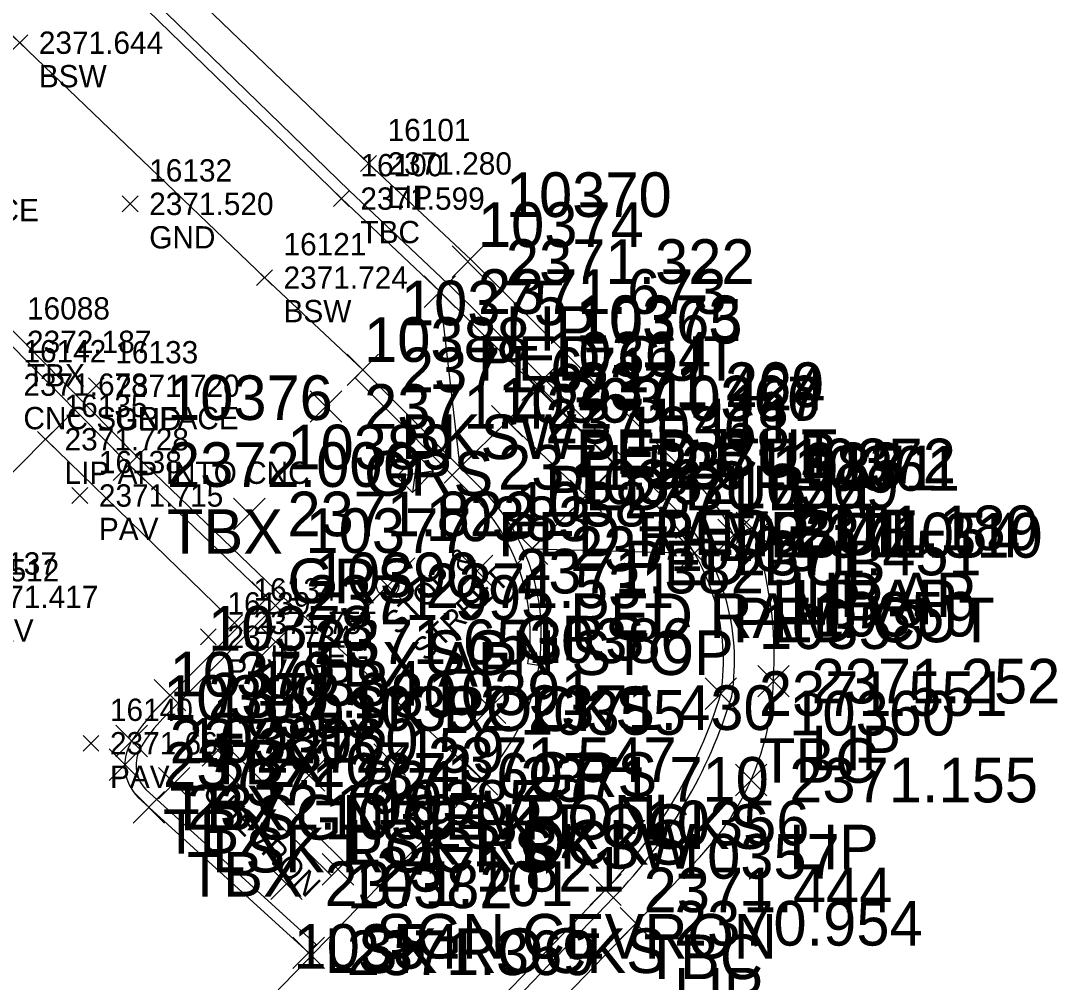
# Model space of a CAD drawing. Extents: x 2377639 to 2379738, y 729875 to 732734.
# Drawn here: x 2378998.89 to 2379045.39, y 731300.7 to 731343.8 of the extents above; entities that cross this region are included whole.
import ezdxf

# ---------------------------------------------------------------- set-up
doc = ezdxf.new("R2010")
doc.units = 0
for name, color, linetype in [('Default', 7, 'Continuous'), ('TOPO_CURBGTR_Back-of-Curb', 7, 'Continuous'), ('TOPO_CURBGTR_Face-of-Curb', 7, 'Continuous'), ('TOPO_CURBGTR_Lip-of-Gutter', 7, 'Continuous'), ('TOPO_DATA_Elevations', 7, 'Continuous'), ('TOPO_DATA_Notes', 7, 'Continuous'), ('TOPO_LNDSCP_Misc', 7, 'Continuous'), ('TOPO_SIGNS_Post-Single', 7, 'Continuous'), ('TOPO_STRUCT_Concrete-Wall', 7, 'Continuous'), ('TOPO_SW_Back', 7, 'Continuous'), ('TOPO_WTRUTIL_Irrig-Box', 7, 'Continuous'), ('TRAF_SIGN_Post', 7, 'Continuous')]:
    doc.layers.add(name, color=color, linetype=linetype)

# ---------------------------------------------------------------- blocks, each defined once
blk = doc.blocks.new('SPRBOX_5')
at = {"layer": 'Default'}
for p, q in [((-0.00857, -0.00643), (0.00857, 0.00643)), ((-0.00857, 0.00643), (0.00857, -0.00643)), ((-0.00857, 0.00643), (0.00857, 0.00643)), ((-0.00857, 0.00643), (-0.00857, -0.00643)), ((0.00857, 0.00643), (0.00857, -0.00643)), ((-0.00857, -0.00643), (0.00857, -0.00643))]:
    blk.add_line(p, q, dxfattribs=at)
blk = doc.blocks.new('STSIGN_4')
at = {"layer": 'Default'}
for p, q in [((0, 0.02226), (0, 0.00635)), ((-0.02226, 0), (-0.00635, 0)), ((0.00635, 0), (0.02226, 0)), ((0, -0.00635), (0, -0.02226))]:
    blk.add_line(p, q, dxfattribs=at)
blk.add_circle((0, 0), 0.00635, dxfattribs=at)

msp = doc.modelspace()

# ---------------------------------------------------------------- linework, layer by layer
at = {"layer": 'TOPO_CURBGTR_Back-of-Curb'}
msp.add_line((2379027.994, 731321.467), (2379017.695, 731331.657), dxfattribs=at)
for points in [[(2378987.114, 731360.909), (2378999.456, 731349.257), (2379013.276, 731335.825), (2379017.695, 731331.657)], [(2378840.2, 731111.439), (2378906.503, 731181.634), (2378954.242, 731230.799), (2378996.057, 731274.46), (2379017.149, 731296.554), (2379025.127, 731304.837)]]:
    msp.add_lwpolyline(points, dxfattribs=at)
for centre, radius, start, end in [((2379020.813, 731315.098), 9.599, 351.2473, 41.5732), ((2379009.353, 731320.03), 21.901, 316.0745, 343.0279)]:
    msp.add_arc(centre, radius, start, end, dxfattribs=at)
at = {"layer": 'TOPO_CURBGTR_Face-of-Curb'}
msp.add_line((2379028.357, 731321.811), (2379018.047, 731332.012), dxfattribs=at)
for points in [[(2378987.457, 731361.273), (2378999.802, 731349.618), (2379013.622, 731336.186), (2379018.038, 731332.021)], [(2378840.546, 731111.077), (2378906.864, 731181.288), (2378954.602, 731230.452), (2378996.418, 731274.114), (2379017.51, 731296.208), (2379025.487, 731304.49)]]:
    msp.add_lwpolyline(points, dxfattribs=at)
for centre, radius, start, end in [((2379020.813, 731315.098), 10.099, 351.042, 41.6668), ((2379009.353, 731320.03), 22.401, 316.0745, 343.1192)]:
    msp.add_arc(centre, radius, start, end, dxfattribs=at)
at = {"layer": 'TOPO_CURBGTR_Lip-of-Gutter'}
for p, q in [((2379029.445, 731322.845), (2379019.102, 731333.079)), ((2379031.697, 731321.064), (2379030.871, 731320.744))]:
    msp.add_line(p, q, dxfattribs=at)
for points in [[(2379019.102, 731333.079), (2379014.495, 731337.4), (2379000.587, 731350.771), (2378988.398, 731362.548)], [(2378843.135, 731111.727), (2378912.115, 731183.979), (2378955.614, 731229.49), (2378997.646, 731273.379), (2379018.593, 731295.17), (2379029.349, 731306.307)]]:
    msp.add_lwpolyline(points, dxfattribs=at)
for centre, radius, start, end in [((2379023.675, 731317.394), 7.938, 24.9615, 43.3723), ((2379015.27, 731315.257), 17.423, 356.507, 19.4705), ((2379020.643, 731314.602), 12.025, 316.386, 358.0598)]:
    msp.add_arc(centre, radius, start, end, dxfattribs=at)
at = {"layer": 'TOPO_DATA_Elevations'}
for p, q in [((2378998.498, 731342.459), (2378999.206, 731343.167)), ((2378998.498, 731343.167), (2378999.206, 731342.459)), ((2378998.498, 731342.459), (2378999.206, 731343.167)), ((2378998.498, 731343.167), (2378999.206, 731342.459)), ((2379014.141, 731337.046), (2379014.849, 731337.754)), ((2379014.141, 731337.754), (2379014.849, 731337.046)), ((2379014.141, 731337.046), (2379014.849, 731337.754)), ((2379014.141, 731337.754), (2379014.849, 731337.046)), ((2379012.922, 731335.471), (2379013.63, 731336.179)), ((2379012.922, 731336.179), (2379013.63, 731335.471)), ((2379012.922, 731335.471), (2379013.63, 731336.179)), ((2379012.922, 731336.179), (2379013.63, 731335.471)), ((2379003.449, 731335.235), (2379004.157, 731335.943)), ((2379003.449, 731335.943), (2379004.157, 731335.235)), ((2379003.449, 731335.235), (2379004.157, 731335.943)), ((2379003.449, 731335.943), (2379004.157, 731335.235)), ((2379018.241, 731332.295), (2379019.655, 731333.709)), ((2379018.241, 731333.709), (2379019.655, 731332.295)), ((2379009.473, 731331.927), (2379010.181, 731332.635)), ((2379009.473, 731332.635), (2379010.181, 731331.927)), ((2379009.473, 731331.927), (2379010.181, 731332.635)), ((2379009.473, 731332.635), (2379010.181, 731331.927)), ((2379016.988, 731330.95), (2379018.402, 731332.364)), ((2379016.988, 731332.364), (2379018.402, 731330.95)), ((2379013.535, 731327.44), (2379014.949, 731328.854)), ((2379013.535, 731328.854), (2379014.949, 731327.44)), ((2379021.373, 731326.775), (2379022.787, 731328.189)), ((2379021.373, 731328.189), (2379022.787, 731326.775)), ((2379001.928, 731327.084), (2379002.636, 731327.792)), ((2379001.928, 731327.792), (2379002.636, 731327.084)), ((2379001.928, 731327.084), (2379002.636, 731327.792)), ((2379001.928, 731327.792), (2379002.636, 731327.084)), ((2379021.416, 731326.62), (2379022.83, 731328.034)), ((2379021.416, 731328.034), (2379022.83, 731326.62)), ((2379011.881, 731325.799), (2379013.295, 731327.213)), ((2379011.881, 731327.213), (2379013.295, 731325.799)), ((2379020.007, 731325.142), (2379021.421, 731326.556)), ((2379020.007, 731326.556), (2379021.421, 731325.142)), ((2378999.652, 731324.682), (2379000.36, 731325.39)), ((2378999.652, 731325.39), (2379000.36, 731324.682)), ((2378999.652, 731324.682), (2379000.36, 731325.39)), ((2378999.652, 731325.39), (2379000.36, 731324.682)), ((2379003.042, 731323.194), (2379004.456, 731324.608)), ((2379003.042, 731324.608), (2379004.456, 731323.194)), ((2379017.892, 731323.075), (2379019.306, 731324.489)), ((2379017.892, 731324.489), (2379019.306, 731323.075)), ((2379024.887, 731323.179), (2379026.301, 731324.593)), ((2379024.887, 731324.593), (2379026.301, 731323.179)), ((2379024.906, 731323.141), (2379026.32, 731324.555)), ((2379024.906, 731324.555), (2379026.32, 731323.141)), ((2379023.537, 731321.787), (2379024.951, 731323.201)), ((2379023.537, 731323.201), (2379024.951, 731321.787)), ((2379001.192, 731322.161), (2379001.9, 731322.869)), ((2379001.192, 731322.869), (2379001.9, 731322.161)), ((2379001.192, 731322.161), (2379001.9, 731322.869)), ((2379001.192, 731322.869), (2379001.9, 731322.161)), ((2379008.443, 731320.982), (2379009.857, 731322.396)), ((2379008.443, 731322.396), (2379009.857, 731320.982)), ((2379030.99, 731320.357), (2379032.404, 731321.771)), ((2379030.99, 731321.771), (2379032.404, 731320.357)), ((2379030.164, 731320.037), (2379031.578, 731321.451)), ((2379030.164, 731321.451), (2379031.578, 731320.037)), ((2379031.163, 731320.023), (2379032.577, 731321.437)), ((2379031.163, 731321.437), (2379032.577, 731320.023)), ((2379021.129, 731319.421), (2379022.543, 731320.835)), ((2379021.129, 731320.835), (2379022.543, 731319.421)), ((2379028.426, 731319.229), (2379029.84, 731320.643)), ((2379028.426, 731320.643), (2379029.84, 731319.229)), ((2379018.661, 731318.42), (2379020.075, 731319.834)), ((2379018.661, 731319.834), (2379020.075, 731318.42)), ((2379014.644, 731317.762), (2379016.058, 731319.176)), ((2379014.644, 731319.176), (2379016.058, 731317.762)), ((2379009.256, 731317.235), (2379010.67, 731318.649)), ((2379009.256, 731318.649), (2379010.67, 731317.235)), ((2379008.131, 731316.451), (2379008.839, 731317.159)), ((2379008.131, 731317.159), (2379008.839, 731316.451)), ((2379008.131, 731316.451), (2379008.839, 731317.159)), ((2379008.131, 731317.159), (2379008.839, 731316.451)), ((2379006.958, 731315.825), (2379007.666, 731316.533)), ((2379006.958, 731316.533), (2379007.666, 731315.825)), ((2379006.958, 731315.825), (2379007.666, 731316.533)), ((2379006.958, 731316.533), (2379007.666, 731315.825)), ((2379009.62, 731315.249), (2379011.034, 731316.663)), ((2379009.62, 731316.663), (2379011.034, 731315.249)), ((2379031.954, 731313.488), (2379033.368, 731314.902)), ((2379031.954, 731314.902), (2379033.368, 731313.488)), ((2379004.884, 731312.857), (2379006.298, 731314.271)), ((2379004.884, 731314.271), (2379006.298, 731312.857)), ((2379029.593, 731312.93), (2379031.007, 731314.344)), ((2379029.593, 731314.344), (2379031.007, 731312.93)), ((2379019.233, 731312.297), (2379020.647, 731313.711)), ((2379019.233, 731313.711), (2379020.647, 731312.297)), ((2379003.161, 731310.801), (2379004.575, 731312.215)), ((2379003.161, 731312.215), (2379004.575, 731310.801)), ((2379001.688, 731311.056), (2379002.396, 731311.764)), ((2379001.688, 731311.764), (2379002.396, 731311.056)), ((2379001.688, 731311.056), (2379002.396, 731311.764)), ((2379001.688, 731311.764), (2379002.396, 731311.056)), ((2379007.026, 731310.383), (2379008.44, 731311.797)), ((2379007.026, 731311.797), (2379008.44, 731310.383)), ((2379014.74, 731309.967), (2379016.154, 731311.381)), ((2379014.74, 731311.381), (2379016.154, 731309.967)), ((2379002.868, 731309.747), (2379004.282, 731311.161)), ((2379002.868, 731311.161), (2379004.282, 731309.747)), ((2379011.117, 731309.261), (2379012.531, 731310.675)), ((2379011.117, 731310.675), (2379012.531, 731309.261)), ((2379018.882, 731309.083), (2379020.296, 731310.497)), ((2379018.882, 731310.497), (2379020.296, 731309.083)), ((2379030.952, 731309.051), (2379032.366, 731310.465)), ((2379030.952, 731310.465), (2379032.366, 731309.051)), ((2379005.068, 731308.913), (2379006.482, 731310.327)), ((2379005.068, 731310.327), (2379006.482, 731308.913)), ((2379003.931, 731307.832), (2379005.345, 731309.246)), ((2379003.931, 731309.246), (2379005.345, 731307.832)), ((2379012.418, 731305.052), (2379013.832, 731306.466)), ((2379012.418, 731306.466), (2379013.832, 731305.052)), ((2379010.111, 731304.403), (2379011.525, 731305.817)), ((2379010.111, 731305.817), (2379011.525, 731304.403)), ((2379024.42, 731304.13), (2379025.834, 731305.544)), ((2379024.42, 731305.544), (2379025.834, 731304.13)), ((2379025.781, 731302.633), (2379027.195, 731304.047)), ((2379025.781, 731304.047), (2379027.195, 731302.633)), ((2379011.103, 731301.31), (2379012.517, 731302.724)), ((2379011.103, 731302.724), (2379012.517, 731301.31))]:
    msp.add_line(p, q, dxfattribs=at)
at = {"layer": 'TOPO_LNDSCP_Misc'}
msp.add_line((2379010.677, 731317.95), (2379019.589, 731309.79), dxfattribs=at)
at = {"layer": 'TOPO_SIGNS_Post-Single'}
msp.add_lwpolyline([(2379008.028, 731311.389), (2379007.438, 731310.791), (2379012.83, 731305.46), (2379013.42, 731306.058)], close=True, dxfattribs=at)
at = {"layer": 'TOPO_STRUCT_Concrete-Wall'}
msp.add_line((2379008.66, 731316.635), (2379000.006, 731325.036), dxfattribs=at)
for points in [[(2379004.095, 731324.262), (2378998.673, 731329.76), (2378986.84, 731341.041), (2378975.107, 731352.58)], [(2379003.749, 731323.901), (2378998.322, 731329.403), (2378986.492, 731340.682), (2378974.756, 731352.223)], [(2379001.336, 731326.348), (2379000.006, 731325.036), (2378994.194, 731319.165)], [(2379003.749, 731323.901), (2379009.963, 731317.942), (2379004.906, 731312.872)], [(2379005.266, 731312.524), (2379010.677, 731317.95), (2379004.095, 731324.262)], [(2379004.162, 731308.977), (2379011.81, 731302.017), (2379012.147, 731302.387), (2379004.509, 731309.337)]]:
    msp.add_lwpolyline(points, dxfattribs=at)
for centre, radius, start, end in [((2379010.967, 731307.182), 8.313, 136.8097, 148.6451), ((2379010.966, 731307.183), 7.812, 136.8636, 148.6443), ((2379005.637, 731310.431), 2.071, 148.6695, 224.5795), ((2379005.637, 731310.431), 1.571, 148.6695, 224.1177)]:
    msp.add_arc(centre, radius, start, end, dxfattribs=at)
at = {"layer": 'TOPO_SW_Back'}
for p, q in [((2379019.883, 731322.497), (2379014.242, 731328.147)), ((2379022.14, 731314.889), (2379021.645, 731314.965)), ((2379009.425, 731299.301), (2379019.589, 731309.79))]:
    msp.add_line(p, q, dxfattribs=at)
for points in [[(2378982.762, 731354.846), (2378985.763, 731351.914), (2378989.945, 731351.256), (2378998.852, 731342.813), (2379009.827, 731332.281), (2379014.242, 731328.147)], [(2379020.714, 731325.849), (2379018.599, 731323.782), (2379017.695, 731331.657)], [(2379019.519, 731322.154), (2379013.888, 731327.794), (2379014.242, 731328.147)], [(2379024.244, 731322.494), (2379021.836, 731320.128), (2379029.103, 731319.937)]]:
    msp.add_lwpolyline(points, dxfattribs=at)
msp.add_lwpolyline([(2379020.714, 731325.849), (2379022.123, 731327.327), (2379025.594, 731323.886), (2379024.244, 731322.494)], close=True, dxfattribs=at)
for radius, start, end in [(8.802, 351.275, 41.6841), (9.302, 315.5796, 41.7732)]:
    msp.add_arc((2379012.946, 731316.3), radius, start, end, dxfattribs=at)

# ---------------------------------------------------------------- block references
at = {"layer": 'TOPO_WTRUTIL_Irrig-Box', "xscale": 78.74000000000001, "yscale": 78.74, "rotation": -135.01160438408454}
msp.add_blockref('SPRBOX_5', (2379016.579, 731323.482), dxfattribs=at)
at = {"layer": 'TRAF_SIGN_Post', "xscale": 78.74, "yscale": 78.74000000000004, "rotation": -134.18600339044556}
msp.add_blockref('STSIGN_4', (2379015.351, 731318.469), dxfattribs=at)

# ---------------------------------------------------------------- texts
at = {"layer": 'TOPO_DATA_Elevations'}
for s, height, p in [('2371.644', 1, (2378999.706, 731342.313)), ('2371.644', 1, (2378999.706, 731342.313)), ('BSW', 1, (2378999.706, 731340.813)), ('BSW', 1, (2378999.706, 731340.813)), ('16101', 1, (2379015.349, 731338.4)), ('16101', 1, (2379015.349, 731338.4)), ('2371.280', 1, (2379015.349, 731336.9)), ('2371.280', 1, (2379015.349, 731336.9)), ('16132', 1, (2379004.657, 731336.589)), ('16132', 1, (2379004.657, 731336.589)), ('16100', 1, (2379014.13, 731336.825)), ('16100', 1, (2379014.13, 731336.825)), ('10370', 2, (2379020.655, 731335.002)), ('2371.520', 1, (2379004.657, 731335.089)), ('2371.520', 1, (2379004.657, 731335.089)), ('2371.599', 1, (2379014.13, 731335.325)), ('2371.599', 1, (2379014.13, 731335.325)), ('LIP', 1, (2379015.349, 731335.4)), ('LIP', 1, (2379015.349, 731335.4)), ('CNC SURFACE', 1, (2378990.048, 731334.81)), ('CNC SURFACE', 1, (2378990.048, 731334.81)), ('10374', 2, (2379019.402, 731333.657)), ('GND', 1, (2379004.657, 731333.589)), ('GND', 1, (2379004.657, 731333.589)), ('TBC', 1, (2379014.13, 731333.825)), ('TBC', 1, (2379014.13, 731333.825)), ('16121', 1, (2379010.681, 731333.281)), ('16121', 1, (2379010.681, 731333.281)), ('2371.322', 2, (2379020.655, 731332.002)), ('2371.724', 1, (2379010.681, 731331.781)), ('2371.724', 1, (2379010.681, 731331.781)), ('2371.673', 2, (2379019.402, 731330.657)), ('10375', 2, (2379015.949, 731330.147)), ('16088', 1, (2378999.176, 731330.403)), ('16088', 1, (2378999.176, 731330.403)), ('10373', 2, (2379023.787, 731329.482)), ('10365', 2, (2379023.83, 731329.327)), ('BSW', 1, (2379010.681, 731330.281)), ('BSW', 1, (2379010.681, 731330.281)), ('LIP', 2, (2379020.655, 731329.002)), ('10388', 2, (2379014.295, 731328.506)), ('16142', 1, (2378999.014, 731328.485)), ('16142', 1, (2378999.014, 731328.485)), ('2372.187', 1, (2378999.176, 731328.903)), ('2372.187', 1, (2378999.176, 731328.903)), ('PED CUT', 2, (2379019.402, 731327.657)), ('10364', 2, (2379022.421, 731327.849)), ('16133', 1, (2379003.136, 731328.438)), ('16133', 1, (2379003.136, 731328.438)), ('2371.671', 2, (2379015.949, 731327.147)), ('TBX', 1, (2378999.176, 731327.403)), ('TBX', 1, (2378999.176, 731327.403)), ('2371.269', 2, (2379023.787, 731326.482)), ('2371.424', 2, (2379023.83, 731326.327)), ('2371.678', 1, (2378999.014, 731326.985)), ('2371.678', 1, (2378999.014, 731326.985)), ('2371.720', 1, (2379003.136, 731326.938)), ('2371.720', 1, (2379003.136, 731326.938)), ('10376', 2, (2379005.456, 731325.901)), ('10363', 2, (2379020.306, 731325.782)), ('10366', 2, (2379027.301, 731325.886)), ('10367', 2, (2379027.32, 731325.848)), ('2371.422', 2, (2379014.295, 731325.506)), ('16135', 1, (2379000.86, 731326.036)), ('16135', 1, (2379000.86, 731326.036)), ('2371.411', 2, (2379022.421, 731324.849)), ('CNC SURFACE', 1, (2378999.014, 731325.485)), ('CNC SURFACE', 1, (2378999.014, 731325.485)), ('GND', 1, (2379003.136, 731325.438)), ('GND', 1, (2379003.136, 731325.438)), ('10368', 2, (2379025.951, 731324.494)), ('BKSW', 2, (2379015.949, 731324.147)), ('2371.728', 1, (2379000.86, 731324.536)), ('2371.728', 1, (2379000.86, 731324.536)), ('10389', 2, (2379010.857, 731323.689)), ('PED CUT', 2, (2379023.787, 731323.482)), ('PED BUB', 2, (2379023.83, 731323.327)), ('2372.006', 2, (2379005.456, 731322.901)), ('2371.383', 2, (2379027.301, 731322.886)), ('2371.415', 2, (2379027.32, 731322.848)), ('10372', 2, (2379033.404, 731323.064)), ('16138', 1, (2379002.4, 731323.515)), ('16138', 1, (2379002.4, 731323.515)), ('GRS', 2, (2379014.295, 731322.506)), ('2371.526', 2, (2379020.306, 731322.782)), ('10371', 2, (2379032.578, 731322.744)), ('10361', 2, (2379033.577, 731322.73)), ('LIP AP INTO CNC', 1, (2379000.86, 731323.036)), ('LIP AP INTO CNC', 1, (2379000.86, 731323.036)), ('10362', 2, (2379023.543, 731322.128)), ('10369', 2, (2379030.84, 731321.936)), ('PED BUB', 2, (2379022.421, 731321.849)), ('2371.444', 2, (2379025.951, 731321.494)), ('2371.715', 1, (2379002.4, 731322.015)), ('2371.715', 1, (2379002.4, 731322.015)), ('10387', 2, (2379021.075, 731321.127)), ('2371.822', 2, (2379010.857, 731320.689)), ('10383', 2, (2379017.058, 731320.469)), ('2371.189', 2, (2379033.404, 731320.064)), ('TBX', 2, (2379005.456, 731319.901)), ('10377', 2, (2379011.67, 731319.942)), ('PED RAMP', 2, (2379020.306, 731319.782)), ('PED BUB', 2, (2379027.301, 731319.886)), ('PED CUT', 2, (2379027.32, 731319.848)), ('2371.054', 2, (2379032.578, 731319.744)), ('2371.310', 2, (2379033.577, 731319.73)), ('PAV', 1, (2379002.4, 731320.515)), ('PAV', 1, (2379002.4, 731320.515)), ('2371.405', 2, (2379023.543, 731319.128)), ('2371.451', 2, (2379030.84, 731318.936)), ('PED BUB', 2, (2379025.951, 731318.494)), ('16137', 1, (2378996.798, 731318.97)), ('16137', 1, (2378996.798, 731318.97)), ('GRS', 2, (2379010.857, 731317.689)), ('10390', 2, (2379012.034, 731317.956)), ('2371.382', 2, (2379021.075, 731318.127)), ('2371.512', 1, (2378995.048, 731318.665)), ('2371.512', 1, (2378995.048, 731318.665)), ('2371.531', 2, (2379017.058, 731317.469)), ('16134', 1, (2379009.339, 731317.805)), ('16134', 1, (2379009.339, 731317.805)), ('2371.995', 2, (2379011.67, 731316.942)), ('LIP AP', 2, (2379033.404, 731317.064)), ('2371.417', 1, (2378996.798, 731317.47)), ('2371.417', 1, (2378996.798, 731317.47)), ('LIP AP', 2, (2379032.578, 731316.744)), ('LIP', 2, (2379033.577, 731316.73)), ('16139', 1, (2379008.166, 731317.179)), ('16139', 1, (2379008.166, 731317.179)), ('PED RAMP', 2, (2379023.543, 731316.128)), ('PED CUT', 2, (2379030.84, 731315.936)), ('10359', 2, (2379034.368, 731316.195)), ('10378', 2, (2379007.298, 731315.564)), ('10358', 2, (2379032.007, 731315.637)), ('PAV', 1, (2378996.798, 731315.97)), ('PAV', 1, (2378996.798, 731315.97)), ('2371.755', 1, (2379009.339, 731316.305)), ('2371.755', 1, (2379009.339, 731316.305)), ('2371.653', 2, (2379012.034, 731314.956)), ('GRS', 2, (2379021.075, 731315.127)), ('10386', 2, (2379021.647, 731315.004)), ('2371.734', 1, (2379008.166, 731315.679)), ('2371.734', 1, (2379008.166, 731315.679)), ('SGN STOP', 2, (2379017.058, 731314.469)), ('10379', 2, (2379005.575, 731313.508)), ('LIP BEG', 1, (2379009.339, 731314.805)), ('LIP BEG', 1, (2379009.339, 731314.805)), ('TBX AP', 2, (2379011.67, 731313.942)), ('PAV', 1, (2379008.166, 731314.179)), ('PAV', 1, (2379008.166, 731314.179)), ('10384', 2, (2379009.44, 731313.09)), ('2371.252', 2, (2379034.368, 731313.195)), ('10391', 2, (2379017.154, 731312.674)), ('2371.551', 2, (2379032.007, 731312.637)), ('10380', 2, (2379005.282, 731312.454)), ('2372.080', 2, (2379007.298, 731312.564)), ('LSK ROCKS', 2, (2379012.034, 731311.956)), ('10392', 2, (2379013.531, 731311.968)), ('10355', 2, (2379021.296, 731311.79)), ('2371.430', 2, (2379021.647, 731312.004)), ('10360', 2, (2379033.366, 731311.758)), ('16140', 1, (2379002.896, 731312.41)), ('16140', 1, (2379002.896, 731312.41)), ('10393', 2, (2379007.482, 731311.62)), ('2372.060', 2, (2379005.575, 731310.508)), ('10381', 2, (2379006.345, 731310.539)), ('2371.663', 1, (2379002.896, 731310.91)), ('2371.663', 1, (2379002.896, 731310.91)), ('2372.159', 2, (2379009.44, 731310.09)), ('LIP', 2, (2379034.368, 731310.195)), ('2372.207', 2, (2379005.282, 731309.454)), ('TBX', 2, (2379007.298, 731309.564)), ('2371.547', 2, (2379017.154, 731309.674)), ('TBC', 2, (2379032.007, 731309.637)), ('2371.607', 2, (2379013.531, 731308.968)), ('GRS', 2, (2379021.647, 731309.004)), ('2371.821', 2, (2379007.482, 731308.62)), ('2371.710', 2, (2379021.296, 731308.79)), ('2371.155', 2, (2379033.366, 731308.758)), ('PAV', 1, (2379002.896, 731309.41)), ('PAV', 1, (2379002.896, 731309.41)), ('TBX', 2, (2379005.575, 731307.508)), ('2372.198', 2, (2379006.345, 731307.539)), ('10385', 2, (2379014.832, 731307.759)), ('SGN CEVRON', 2, (2379009.44, 731307.09)), ('10394', 2, (2379012.525, 731307.11)), ('LSK ROCKS', 2, (2379017.154, 731306.674)), ('10356', 2, (2379026.834, 731306.837)), ('TBX', 2, (2379005.282, 731306.454)), ('LSK ROCKS', 2, (2379007.482, 731305.62)), ('LSK ROCKS', 2, (2379013.531, 731305.968)), ('BKSW', 2, (2379021.296, 731305.79)), ('LIP', 2, (2379033.366, 731305.758)), ('10357', 2, (2379028.195, 731305.34)), ('2371.821', 2, (2379014.832, 731304.759)), ('TBX', 2, (2379006.345, 731304.539)), ('2371.701', 2, (2379012.525, 731304.11)), ('10382', 2, (2379013.517, 731304.017)), ('2371.444', 2, (2379026.834, 731303.837)), ('2370.954', 2, (2379028.195, 731302.34)), ('SGN CEVRON', 2, (2379014.832, 731301.759)), ('10354', 2, (2379011.132, 731301.301)), ('LSK ROCKS', 2, (2379012.525, 731301.11)), ('2371.369', 2, (2379013.517, 731301.017)), ('TBC', 2, (2379026.834, 731300.837)), ('LIP', 2, (2379028.195, 731299.34))]:
    msp.add_text(s, height=height, dxfattribs=at).set_placement(p)
at = {"layer": 'TOPO_DATA_Notes'}
for s, rotation, p in [('STOP &', 43.5991, (2379015.778, 731316.223)), ('STREET', 43.5991, (2379017.059, 731315.038)), ('CHEVRON', 315.3259, (2379006.975, 731309.147))]:
    msp.add_text(s, height=1, rotation=rotation, dxfattribs=at).set_placement(p)

doc.saveas('drawing.dxf')
